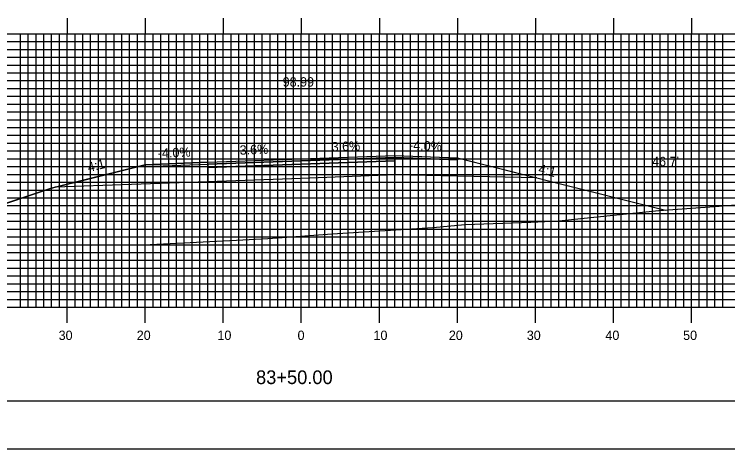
# Model space of a CAD drawing. Extents: x 1763365 to 1763708, y 442591 to 442811.
# Drawn here: x 1763494 to 1763585.5, y 442590.5 to 442646.2 of the extents above; entities that cross this region are included whole.
import ezdxf

# ---------------------------------------------------------------- set-up
doc = ezdxf.new("R2010")
doc.units = 0
for name, color, linetype in [('ANNOTATION', 7, 'Continuous'), ('BORDER', 7, 'Continuous'), ('D_Roadway_Centerline', 7, 'Continuous'), ('D_Roadway_Centerline_Text', 7, 'Continuous'), ('D_Roadway_Edge_Shoulder', 7, 'Continuous'), ('D_Roadway_Edge_TW', 7, 'Continuous'), ('D_Roadway_Pavement', 7, 'Continuous'), ('D_Roadway_SlopeLines', 7, 'Continuous'), ('D_Roadway_SubGrade', 7, 'Continuous'), ('D_Text_Standard', 7, 'Continuous'), ('H_V ANNOTATION', 7, 'Continuous'), ('MAJOR', 7, 'Continuous'), ('MINOR', 7, 'Continuous'), ('PLOT BOUNDARY', 7, 'Continuous'), ('S_Roadway_Centerline', 7, 'Continuous')]:
    doc.layers.add(name, color=color, linetype=linetype)

msp = doc.modelspace()

# ---------------------------------------------------------------- linework, layer by layer
at = {"layer": 'BORDER'}
msp.add_lwpolyline([(1763381.205, 442596.665), (1763701.205, 442596.665), (1763701.205, 442806.665), (1763381.205, 442806.665)], close=True, dxfattribs=at)
at = {"layer": 'D_Roadway_Centerline'}
msp.add_lwpolyline([(1763475.722, 442616.208), (1763481.912, 442618.272), (1763498.805, 442623.903), (1763499.25, 442624.014), (1763499.273, 442624.019), (1763502.085, 442624.722), (1763510.806, 442626.903), (1763518.806, 442627.223), (1763530.806, 442627.655), (1763542.805, 442628.087), (1763550.805, 442627.767), (1763553.003, 442627.218), (1763560.977, 442625.224), (1763560.979, 442625.223), (1763562.806, 442624.767), (1763562.811, 442624.766), (1763577.458, 442621.103)], dxfattribs=at)
at = {"layer": 'D_Roadway_Edge_Shoulder'}
for points in [[(1763542.805, 442628.087), (1763550.805, 442627.767), (1763550.805, 442627.517), (1763542.805, 442627.837)], [(1763518.806, 442627.223), (1763510.806, 442626.903), (1763510.806, 442626.653), (1763518.806, 442626.973)]]:
    msp.add_lwpolyline(points, close=True, dxfattribs=at)
at = {"layer": 'D_Roadway_Edge_TW'}
for points in [[(1763518.806, 442626.973), (1763518.806, 442627.223), (1763530.806, 442627.655), (1763542.805, 442628.087), (1763542.805, 442627.837), (1763530.806, 442627.405)], [(1763542.805, 442628.087), (1763542.805, 442628.087), (1763542.805, 442627.837), (1763542.805, 442627.837)]]:
    msp.add_lwpolyline(points, close=True, dxfattribs=at)
at = {"layer": 'D_Roadway_Pavement'}
for points in [[(1763518.806, 442626.556), (1763518.806, 442626.973), (1763530.806, 442627.405), (1763542.805, 442627.837), (1763542.805, 442627.42), (1763530.806, 442626.988)], [(1763542.805, 442627.837), (1763542.805, 442627.837), (1763542.805, 442627.42), (1763542.805, 442627.42)]]:
    msp.add_lwpolyline(points, close=True, dxfattribs=at)
msp.add_lwpolyline([(1763542.805, 442627.837), (1763542.805, 442627.42)], dxfattribs=at)
msp.add_lwpolyline([(1763542.805, 442627.837), (1763542.805, 442627.42)], dxfattribs=at)
msp.add_lwpolyline([(1763542.805, 442627.837), (1763542.805, 442627.42)], dxfattribs=at)
at = {"layer": 'D_Roadway_SlopeLines'}
for points in [[(1763550.805, 442627.767), (1763560.979, 442625.223), (1763562.806, 442624.767), (1763577.458, 442621.103)], [(1763510.806, 442626.903), (1763498.805, 442623.903), (1763475.722, 442616.208)]]:
    msp.add_lwpolyline(points, dxfattribs=at)
at = {"layer": 'D_Roadway_SubGrade'}
for points in [[(1763542.805, 442627.42), (1763542.805, 442627.837), (1763550.805, 442627.517), (1763550.805, 442627.767), (1763560.979, 442625.223), (1763542.805, 442625.587)], [(1763510.806, 442626.653), (1763518.806, 442626.973), (1763518.806, 442626.556), (1763518.806, 442624.723), (1763499.273, 442624.019), (1763510.806, 442626.903)], [(1763518.806, 442624.723), (1763518.806, 442626.556), (1763530.806, 442626.988), (1763542.805, 442627.42), (1763542.805, 442625.587), (1763530.806, 442625.155)], [(1763542.805, 442627.42), (1763542.805, 442627.42), (1763542.805, 442625.587), (1763542.805, 442625.587)]]:
    msp.add_lwpolyline(points, close=True, dxfattribs=at)
at = {"layer": 'MAJOR'}
for p, q in [((1763500.805, 442645.669), (1763500.805, 442643.665)), ((1763510.805, 442645.669), (1763510.805, 442643.665)), ((1763520.805, 442645.669), (1763520.805, 442643.665)), ((1763530.805, 442645.669), (1763530.805, 442643.665)), ((1763540.805, 442645.669), (1763540.805, 442643.665)), ((1763550.805, 442645.669), (1763550.805, 442643.665)), ((1763560.805, 442645.669), (1763560.805, 442643.665)), ((1763570.805, 442645.669), (1763570.805, 442643.665)), ((1763580.805, 442645.669), (1763580.805, 442643.665)), ((1763390.805, 442643.665), (1763670.805, 442643.665)), ((1763390.805, 442643.665), (1763670.805, 442643.665)), ((1763500.805, 442608.665), (1763500.805, 442643.665)), ((1763510.805, 442608.665), (1763510.805, 442643.665)), ((1763520.805, 442608.665), (1763520.805, 442643.665)), ((1763530.805, 442608.665), (1763530.805, 442643.665)), ((1763540.805, 442608.665), (1763540.805, 442643.665)), ((1763550.805, 442608.665), (1763550.805, 442643.665)), ((1763560.805, 442608.665), (1763560.805, 442643.665)), ((1763570.805, 442608.665), (1763570.805, 442643.665)), ((1763580.805, 442608.665), (1763580.805, 442643.665)), ((1763390.805, 442638.665), (1763670.805, 442638.665)), ((1763390.805, 442633.665), (1763670.805, 442633.665)), ((1763390.805, 442628.665), (1763670.805, 442628.665)), ((1763390.805, 442623.665), (1763670.805, 442623.665)), ((1763390.805, 442618.665), (1763670.805, 442618.665)), ((1763390.805, 442613.665), (1763670.805, 442613.665)), ((1763390.805, 442608.665), (1763670.805, 442608.665)), ((1763390.805, 442608.665), (1763670.805, 442608.665)), ((1763500.805, 442606.661), (1763500.805, 442608.665)), ((1763510.805, 442606.661), (1763510.805, 442608.665)), ((1763520.805, 442606.661), (1763520.805, 442608.665)), ((1763530.805, 442606.661), (1763530.805, 442608.665)), ((1763540.805, 442606.661), (1763540.805, 442608.665)), ((1763550.805, 442606.661), (1763550.805, 442608.665)), ((1763560.805, 442606.661), (1763560.805, 442608.665)), ((1763570.805, 442606.661), (1763570.805, 442608.665)), ((1763580.805, 442606.661), (1763580.805, 442608.665))]:
    msp.add_line(p, q, dxfattribs=at)
at = {"layer": 'MINOR'}
for p, q in [((1763494.805, 442608.665), (1763494.805, 442643.665)), ((1763495.805, 442608.665), (1763495.805, 442643.665)), ((1763496.805, 442608.665), (1763496.805, 442643.665)), ((1763497.805, 442608.665), (1763497.805, 442643.665)), ((1763498.805, 442608.665), (1763498.805, 442643.665)), ((1763499.805, 442608.665), (1763499.805, 442643.665)), ((1763501.805, 442608.665), (1763501.805, 442643.665)), ((1763502.805, 442608.665), (1763502.805, 442643.665)), ((1763503.805, 442608.665), (1763503.805, 442643.665)), ((1763504.805, 442608.665), (1763504.805, 442643.665)), ((1763505.805, 442608.665), (1763505.805, 442643.665)), ((1763506.805, 442608.665), (1763506.805, 442643.665)), ((1763507.805, 442608.665), (1763507.805, 442643.665)), ((1763508.805, 442608.665), (1763508.805, 442643.665)), ((1763509.805, 442608.665), (1763509.805, 442643.665)), ((1763511.805, 442608.665), (1763511.805, 442643.665)), ((1763512.805, 442608.665), (1763512.805, 442643.665)), ((1763513.805, 442608.665), (1763513.805, 442643.665)), ((1763514.805, 442608.665), (1763514.805, 442643.665)), ((1763515.805, 442608.665), (1763515.805, 442643.665)), ((1763516.805, 442608.665), (1763516.805, 442643.665)), ((1763517.805, 442608.665), (1763517.805, 442643.665)), ((1763518.805, 442608.665), (1763518.805, 442643.665)), ((1763519.805, 442608.665), (1763519.805, 442643.665)), ((1763521.805, 442608.665), (1763521.805, 442643.665)), ((1763522.805, 442608.665), (1763522.805, 442643.665)), ((1763523.805, 442608.665), (1763523.805, 442643.665)), ((1763524.805, 442608.665), (1763524.805, 442643.665)), ((1763525.805, 442608.665), (1763525.805, 442643.665)), ((1763526.805, 442608.665), (1763526.805, 442643.665)), ((1763527.805, 442608.665), (1763527.805, 442643.665)), ((1763528.805, 442608.665), (1763528.805, 442643.665)), ((1763529.805, 442608.665), (1763529.805, 442643.665)), ((1763531.805, 442608.665), (1763531.805, 442643.665)), ((1763532.805, 442608.665), (1763532.805, 442643.665)), ((1763533.805, 442608.665), (1763533.805, 442643.665)), ((1763534.805, 442608.665), (1763534.805, 442643.665)), ((1763535.805, 442608.665), (1763535.805, 442643.665)), ((1763536.805, 442608.665), (1763536.805, 442643.665)), ((1763537.805, 442608.665), (1763537.805, 442643.665)), ((1763538.805, 442608.665), (1763538.805, 442643.665)), ((1763539.805, 442608.665), (1763539.805, 442643.665)), ((1763541.805, 442608.665), (1763541.805, 442643.665)), ((1763542.805, 442608.665), (1763542.805, 442643.665)), ((1763543.805, 442608.665), (1763543.805, 442643.665)), ((1763544.805, 442608.665), (1763544.805, 442643.665)), ((1763545.805, 442608.665), (1763545.805, 442643.665)), ((1763546.805, 442608.665), (1763546.805, 442643.665)), ((1763547.805, 442608.665), (1763547.805, 442643.665)), ((1763548.805, 442608.665), (1763548.805, 442643.665)), ((1763549.805, 442608.665), (1763549.805, 442643.665)), ((1763551.805, 442608.665), (1763551.805, 442643.665)), ((1763552.805, 442608.665), (1763552.805, 442643.665)), ((1763553.805, 442608.665), (1763553.805, 442643.665)), ((1763554.805, 442608.665), (1763554.805, 442643.665)), ((1763555.805, 442608.665), (1763555.805, 442643.665)), ((1763556.805, 442608.665), (1763556.805, 442643.665)), ((1763557.805, 442608.665), (1763557.805, 442643.665)), ((1763558.805, 442608.665), (1763558.805, 442643.665)), ((1763559.805, 442608.665), (1763559.805, 442643.665)), ((1763561.805, 442608.665), (1763561.805, 442643.665)), ((1763562.805, 442608.665), (1763562.805, 442643.665)), ((1763563.805, 442608.665), (1763563.805, 442643.665)), ((1763564.805, 442608.665), (1763564.805, 442643.665)), ((1763565.805, 442608.665), (1763565.805, 442643.665)), ((1763566.805, 442608.665), (1763566.805, 442643.665)), ((1763567.805, 442608.665), (1763567.805, 442643.665)), ((1763568.805, 442608.665), (1763568.805, 442643.665)), ((1763569.805, 442608.665), (1763569.805, 442643.665)), ((1763571.805, 442608.665), (1763571.805, 442643.665)), ((1763572.805, 442608.665), (1763572.805, 442643.665)), ((1763573.805, 442608.665), (1763573.805, 442643.665)), ((1763574.805, 442608.665), (1763574.805, 442643.665)), ((1763575.805, 442608.665), (1763575.805, 442643.665)), ((1763576.805, 442608.665), (1763576.805, 442643.665)), ((1763577.805, 442608.665), (1763577.805, 442643.665)), ((1763578.805, 442608.665), (1763578.805, 442643.665)), ((1763579.805, 442608.665), (1763579.805, 442643.665)), ((1763581.805, 442608.665), (1763581.805, 442643.665)), ((1763582.805, 442608.665), (1763582.805, 442643.665)), ((1763583.805, 442608.665), (1763583.805, 442643.665)), ((1763584.805, 442608.665), (1763584.805, 442643.665)), ((1763390.805, 442642.665), (1763670.805, 442642.665)), ((1763390.805, 442641.665), (1763670.805, 442641.665)), ((1763390.805, 442640.665), (1763670.805, 442640.665)), ((1763390.805, 442639.665), (1763670.805, 442639.665)), ((1763390.805, 442637.665), (1763670.805, 442637.665)), ((1763390.805, 442636.665), (1763670.805, 442636.665)), ((1763390.805, 442635.665), (1763670.805, 442635.665)), ((1763390.805, 442634.665), (1763670.805, 442634.665)), ((1763390.805, 442632.665), (1763670.805, 442632.665)), ((1763390.805, 442631.665), (1763670.805, 442631.665)), ((1763390.805, 442630.665), (1763670.805, 442630.665)), ((1763390.805, 442629.665), (1763670.805, 442629.665)), ((1763390.805, 442627.665), (1763670.805, 442627.665)), ((1763390.805, 442626.665), (1763670.805, 442626.665)), ((1763390.805, 442625.665), (1763670.805, 442625.665)), ((1763390.805, 442624.665), (1763670.805, 442624.665)), ((1763390.805, 442622.665), (1763670.805, 442622.665)), ((1763390.805, 442621.665), (1763670.805, 442621.665)), ((1763390.805, 442620.665), (1763670.805, 442620.665)), ((1763390.805, 442619.665), (1763670.805, 442619.665)), ((1763390.805, 442617.665), (1763670.805, 442617.665)), ((1763390.805, 442616.665), (1763670.805, 442616.665)), ((1763390.805, 442615.665), (1763670.805, 442615.665)), ((1763390.805, 442614.665), (1763670.805, 442614.665)), ((1763390.805, 442612.665), (1763670.805, 442612.665)), ((1763390.805, 442611.665), (1763670.805, 442611.665)), ((1763390.805, 442610.665), (1763670.805, 442610.665)), ((1763390.805, 442609.665), (1763670.805, 442609.665))]:
    msp.add_line(p, q, dxfattribs=at)
at = {"layer": 'PLOT BOUNDARY'}
msp.add_lwpolyline([(1763365.019, 442590.547), (1763705.019, 442590.547), (1763705.019, 442810.547), (1763365.019, 442810.547)], close=True, dxfattribs=at)
at = {"layer": 'S_Roadway_Centerline'}
msp.add_lwpolyline([(1763492.614, 442616.67), (1763503.928, 442616.618), (1763511.42, 442616.7), (1763522.513, 442617.226), (1763526.504, 442617.442), (1763528.366, 442617.587), (1763534.751, 442618.05), (1763547.658, 442618.851), (1763551.818, 442619.24), (1763560.233, 442619.54), (1763563.839, 442619.731), (1763565.805, 442619.911), (1763576.606, 442621.042), (1763584.372, 442621.603), (1763595.431, 442622.501)], dxfattribs=at)

# ---------------------------------------------------------------- texts
at = {"layer": 'ANNOTATION'}
for s, rotation, p in [('3.6%', 2.06181, (1763534.712, 442628.597)), ('-4.0%', 357.70934, (1763544.597, 442628.817)), ('-4.0%', 2.29066, (1763512.438, 442627.77)), ('-3.6%', 2.06181, (1763522.392, 442628.154)), ('4:1', 14.03944, (1763503.575, 442625.957)), ('4:1', 345.96076, (1763561.1, 442625.846))]:
    msp.add_text(s, height=1.2, rotation=rotation, dxfattribs=at).set_placement(p)
at = {"layer": 'D_Roadway_Centerline'}
for s, p in [('C', (1763530.8, 442627.655)), ('L', (1763530.806, 442627.648))]:
    msp.add_text(s, height=0.0146, dxfattribs=at).set_placement(p)
at = {"layer": 'D_Roadway_Centerline_Text'}
msp.add_text('98.99', height=1.2, dxfattribs=at).set_placement((1763528.419, 442636.902))
at = {"layer": 'D_Text_Standard'}
msp.add_text("46.7'", height=1.2, dxfattribs=at).set_placement((1763575.763, 442626.712))
at = {"layer": 'H_V ANNOTATION'}
for s, height, p in [('30', 1.2, (1763499.703, 442604.465)), ('20', 1.2, (1763509.713, 442604.465)), ('10', 1.2, (1763520.056, 442604.465)), ('0', 1.2, (1763530.324, 442604.465)), ('10', 1.2, (1763540.056, 442604.465)), ('20', 1.2, (1763549.713, 442604.465)), ('30', 1.2, (1763559.703, 442604.465)), ('40', 1.2, (1763569.778, 442604.465)), ('50', 1.2, (1763579.735, 442604.465)), ('83+50.00', 1.75, (1763525, 442598.821))]:
    msp.add_text(s, height=height, dxfattribs=at).set_placement(p)

doc.saveas('drawing.dxf')
